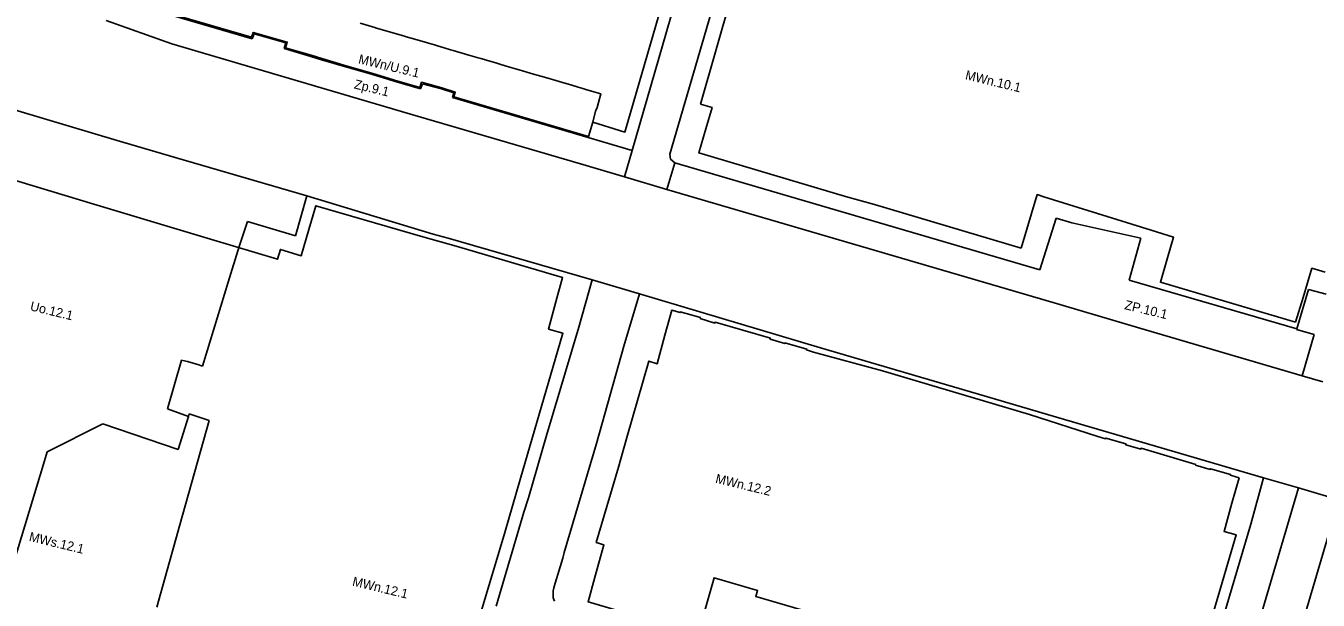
# Model space of a CAD drawing. Extents: x 7429686 to 7432896, y 5547954 to 5550600.
# Drawn here: x 7431434 to 7431990, y 5548459 to 5548706 of the extents above; entities that cross this region are included whole.
import ezdxf

# ---------------------------------------------------------------- set-up
doc = ezdxf.new("R2010")
doc.units = 0
for name, color, linetype in [('linie rozgraniczające', 7, 'Continuous'), ('obowiązująca linia zabudowy', 7, 'Continuous'), ('oznaczenia przeznaczeń', 7, 'Continuous')]:
    doc.layers.add(name, color=color, linetype=linetype)

msp = doc.modelspace()

# ---------------------------------------------------------------- linework, layer by layer
at = {"layer": 'linie rozgraniczające'}
for p, q in [((7431577.76, 5548707.2), (7431584.04, 5548705.36)), ((7431584.04, 5548705.36), (7431584.23, 5548705.3)), ((7431584.23, 5548705.3), (7431590.71, 5548703.4)), ((7431590.71, 5548703.4), (7431594.39, 5548702.33)), ((7431594.39, 5548702.33), (7431597.18, 5548701.51)), ((7431597.18, 5548701.51), (7431597.49, 5548701.42)), ((7431597.49, 5548701.42), (7431600.27, 5548700.6)), ((7431600.27, 5548700.6), (7431603.65, 5548699.61)), ((7431603.65, 5548699.61), (7431604.22, 5548699.45)), ((7431604.22, 5548699.45), (7431606.71, 5548698.72)), ((7431606.71, 5548698.72), (7431610.12, 5548697.72)), ((7431610.12, 5548697.72), (7431610.94, 5548697.48)), ((7431610.94, 5548697.48), (7431613.89, 5548696.61)), ((7431613.89, 5548696.61), (7431616.59, 5548695.82)), ((7431616.59, 5548695.82), (7431617.67, 5548695.51)), ((7431617.67, 5548695.51), (7431623.06, 5548693.93)), ((7431623.06, 5548693.93), (7431624.39, 5548693.54)), ((7431624.39, 5548693.54), (7431628.4, 5548692.36)), ((7431628.4, 5548692.36), (7431629.54, 5548692.03)), ((7431631.5, 5548691.45), (7431636.01, 5548690.13)), ((7431636.01, 5548690.13), (7431637.84, 5548689.6)), ((7431637.84, 5548689.6), (7431640.09, 5548688.94)), ((7431640.09, 5548688.94), (7431642.48, 5548688.24)), ((7431642.48, 5548688.24), (7431644.57, 5548687.63)), ((7431644.57, 5548687.63), (7431645.12, 5548687.46)), ((7431645.12, 5548687.46), (7431648.95, 5548686.34)), ((7431648.95, 5548686.34), (7431651.29, 5548685.66)), ((7431658.01, 5548683.69), (7431661.89, 5548682.55)), ((7431661.89, 5548682.55), (7431664.74, 5548681.72)), ((7431664.74, 5548681.72), (7431668.37, 5548680.65)), ((7431668.37, 5548680.65), (7431671.46, 5548679.75)), ((7431671.46, 5548679.75), (7431673.47, 5548679.16)), ((7431673.47, 5548679.16), (7431674.84, 5548678.76)), ((7431681.2, 5548676.79), (7431680.21, 5548673.18)), ((7431681.22, 5548676.89), (7431681.2, 5548676.79)), ((7431675.72, 5548658.05), (7431617.39, 5548675.21)), ((7431678.98, 5548669.34), (7431677.77, 5548664.65)), ((7431679.1, 5548669.64), (7431678.98, 5548669.34)), ((7431677.77, 5548664.65), (7431675.86, 5548658.53)), ((7431675.86, 5548658.53), (7431675.72, 5548658.05)), ((7431675.72, 5548658.05), (7431694.68, 5548652.52))]:
    msp.add_line(p, q, dxfattribs=at)
for points in [[(7431503.63, 5548920.58), (7431505.97, 5548918), (7431509.04, 5548914.81), (7431512.23, 5548911.8), (7431515.52, 5548908.91), (7431518.64, 5548906.47), (7431521.8, 5548904.16), (7431525.48, 5548901.64), (7431528.82, 5548899.44), (7431532.17, 5548897.4), (7431535.64, 5548895.42), (7431539.13, 5548893.58), (7431542.89, 5548892), (7431546.65, 5548890.61), (7431554.28, 5548888.03), (7431569.39, 5548883.24), (7431746.47, 5548831.23), (7431732.49, 5548783.01), (7431694.68, 5548652.52)], [(7431694.68, 5548652.52), (7431732.49, 5548783.01), (7431746.47, 5548831.23)], [(7431710.91, 5548650.94), (7431731.33, 5548720.67)], [(7431531.3, 5548700.57), (7431472.83, 5548717.66)], [(7431496.71, 5548698.43), (7431468.45, 5548708.34)], [(7431675.72, 5548658.05), (7431675.86, 5548658.53), (7431675.86, 5548658.53), (7431677.77, 5548664.65), (7431678.98, 5548669.34), (7431679.1, 5548669.64), (7431679.6, 5548670.96), (7431680.21, 5548673.18), (7431681.2, 5548676.79), (7431681.22, 5548676.89), (7431678.19, 5548677.78), (7431674.84, 5548678.76), (7431673.47, 5548679.16), (7431671.46, 5548679.75), (7431668.37, 5548680.65), (7431664.74, 5548681.72), (7431661.89, 5548682.55), (7431658.01, 5548683.69), (7431655.42, 5548684.45), (7431651.29, 5548685.66), (7431648.95, 5548686.34), (7431645.12, 5548687.46), (7431644.57, 5548687.63), (7431642.48, 5548688.24), (7431640.09, 5548688.94), (7431637.84, 5548689.6), (7431636.01, 5548690.13), (7431631.5, 5548691.45), (7431631.12, 5548691.57), (7431629.54, 5548692.03), (7431628.4, 5548692.36), (7431624.39, 5548693.54), (7431623.06, 5548693.93), (7431617.67, 5548695.51), (7431616.59, 5548695.82), (7431613.89, 5548696.61), (7431610.94, 5548697.48), (7431610.12, 5548697.72), (7431606.71, 5548698.72), (7431604.22, 5548699.45), (7431603.65, 5548699.61), (7431600.27, 5548700.6), (7431597.49, 5548701.42), (7431597.18, 5548701.51), (7431594.39, 5548702.33), (7431590.71, 5548703.4), (7431584.23, 5548705.3), (7431584.04, 5548705.36), (7431577.76, 5548707.2)], [(7431600.36, 5548667.76), (7431496.71, 5548698.43)], [(7431532.03, 5548702.66), (7431531.3, 5548700.57)], [(7431545.69, 5548698.76), (7431532.03, 5548702.66)], [(7431544.95, 5548696.35), (7431545.69, 5548698.76)], [(7431556.43, 5548692.95), (7431544.95, 5548696.35)], [(7431561.06, 5548691.54), (7431556.43, 5548692.95)], [(7431571.9, 5548688.31), (7431561.06, 5548691.54)], [(7431581.54, 5548685.54), (7431571.9, 5548688.31)], [(7431629.54, 5548692.03), (7431631.12, 5548691.57), (7431631.5, 5548691.45)], [(7431587.72, 5548683.7), (7431581.54, 5548685.54)], [(7431592.37, 5548682.28), (7431587.72, 5548683.7)], [(7431603.71, 5548678.98), (7431592.37, 5548682.28)], [(7431651.29, 5548685.66), (7431655.42, 5548684.45), (7431658.01, 5548683.69)], [(7431604.45, 5548681.2), (7431603.71, 5548678.98)], [(7431612.66, 5548678.95), (7431604.45, 5548681.2)], [(7431617.97, 5548677.21), (7431612.66, 5548678.95)], [(7431617.39, 5548675.21), (7431617.97, 5548677.21)], [(7431674.84, 5548678.76), (7431678.19, 5548677.78), (7431681.22, 5548676.89)], [(7431420.72, 5548672.35), (7431473.1, 5548656.83)], [(7431680.21, 5548673.18), (7431679.6, 5548670.96), (7431679.1, 5548669.64)], [(7431672.44, 5548646.7), (7431600.36, 5548667.76)], [(7431473.1, 5548656.83), (7431498.14, 5548649.42)], [(7431694.68, 5548652.52), (7431675.72, 5548658.05)], [(7431498.14, 5548649.42), (7431554.76, 5548632.95)], [(7431691.39, 5548641.16), (7431694.68, 5548652.52)], [(7431711.13, 5548648.69), (7431710.91, 5548650.94)], [(7431713.04, 5548647.14), (7431711.13, 5548648.69)], [(7431691.39, 5548641.16), (7431672.44, 5548646.7)], [(7431709.65, 5548635.7), (7431713.04, 5548647.14)], [(7431870.15, 5548601.12), (7431713.04, 5548647.14)], [(7431709.65, 5548635.7), (7431691.39, 5548641.16)], [(7431549.94, 5548615.77), (7431554.76, 5548632.95)], [(7431554.76, 5548632.95), (7431609.14, 5548616.53)], [(7431876.24, 5548586.9), (7431709.65, 5548635.7)], [(7431525.64, 5548611.13), (7431529.21, 5548621.93)], [(7431529.21, 5548621.93), (7431549.94, 5548615.77)], [(7431877.06, 5548623.35), (7431870.15, 5548601.12)], [(7431883.87, 5548621.35), (7431877.06, 5548623.35)], [(7431913.57, 5548614.73), (7431883.87, 5548621.35)], [(7431609.14, 5548616.53), (7431615.49, 5548614.69)], [(7431520.93, 5548595.86), (7431525.64, 5548611.13)], [(7431615.49, 5548614.69), (7431677.48, 5548596.82)], [(7431908.52, 5548596.75), (7431913.57, 5548614.73)], [(7431509.85, 5548559.63), (7431520.93, 5548595.86)], [(7431671.82, 5548576.51), (7431677.48, 5548596.82)], [(7431677.48, 5548596.82), (7431697.81, 5548590.8)], [(7431980.62, 5548575.7), (7431908.52, 5548596.75)], [(7431980.62, 5548575.7), (7431985.71, 5548592.71)], [(7431985.71, 5548592.71), (7431993.32, 5548590.62)], [(7431691.12, 5548568.26), (7431697.81, 5548590.8)], [(7431697.81, 5548590.8), (7431775.77, 5548567.61)], [(7431915.54, 5548575.38), (7431876.24, 5548586.9)], [(7431657.81, 5548529.79), (7431671.82, 5548576.51)], [(7431982.95, 5548555.5), (7431915.54, 5548575.38)], [(7431980.55, 5548575.45), (7431980.62, 5548575.7)], [(7431988.11, 5548573.3), (7431980.55, 5548575.45)], [(7431982.95, 5548555.5), (7431988.11, 5548573.3)], [(7431679.35, 5548526.44), (7431691.12, 5548568.26)], [(7431775.77, 5548567.61), (7431846.2, 5548546.87)], [(7431494.74, 5548541.27), (7431500.84, 5548562.3)], [(7431500.84, 5548562.3), (7431502.63, 5548561.86)], [(7431502.63, 5548561.86), (7431503.34, 5548561.65)], [(7431503.34, 5548561.65), (7431508.26, 5548560.22)], [(7431508.26, 5548560.22), (7431509, 5548559.99)], [(7431509, 5548559.99), (7431509.85, 5548559.63)], [(7431991.83, 5548552.89), (7431982.95, 5548555.5)], [(7431846.2, 5548546.87), (7431878.25, 5548537.41)], [(7431503.78, 5548538.02), (7431494.74, 5548541.27)], [(7431499.42, 5548523.89), (7431503.78, 5548538.02)], [(7431504.16, 5548539.22), (7431503.78, 5548538.02)], [(7431512.66, 5548536.29), (7431504.16, 5548539.22)], [(7431878.25, 5548537.41), (7431966.32, 5548511.58)], [(7431443.04, 5548522.77), (7431467.02, 5548534.9)], [(7431467.02, 5548534.9), (7431499.42, 5548523.89)], [(7431500.07, 5548491.36), (7431512.66, 5548536.29)], [(7431650.1, 5548503.07), (7431657.81, 5548529.79)], [(7431665.5, 5548479.5), (7431679.35, 5548526.44)], [(7431441.87, 5548518.94), (7431443.04, 5548522.77)], [(7431426.79, 5548469.23), (7431441.87, 5548518.94)], [(7431960.89, 5548491.66), (7431966.32, 5548511.58)], [(7431966.32, 5548511.58), (7431981.35, 5548507.31)], [(7431957.96, 5548428.04), (7431981.35, 5548507.31)], [(7431981.35, 5548507.31), (7432021.76, 5548495.37)], [(7431648.03, 5548496.92), (7431650.1, 5548503.07)], [(7431636.27, 5548456.43), (7431648.03, 5548496.92)], [(7431490.15, 5548455.95), (7431500.07, 5548491.36)], [(7431934.9, 5548404.14), (7431960.89, 5548491.66)], [(7431661.54, 5548466.27), (7431664.9, 5548477.02)], [(7431664.9, 5548477.02), (7431665.5, 5548479.5)], [(7431661.05, 5548464.33), (7431661.54, 5548466.27)], [(7431660.67, 5548461.65), (7431660.76, 5548462.99)], [(7431660.79, 5548460.09), (7431660.67, 5548461.65)], [(7431660.76, 5548462.99), (7431661.05, 5548464.33)], [(7431661.32, 5548458.6), (7431660.79, 5548460.09)]]:
    msp.add_lwpolyline(points, dxfattribs=at)
at = {"layer": 'obowiązująca linia zabudowy'}
for points in [[(7431773.26, 5548819.35), (7431770.21, 5548808.72), (7431766.52, 5548795.89), (7431760.63, 5548797.5), (7431747.1, 5548751.63), (7431737.24, 5548718.65), (7431724.14, 5548672.46)], [(7431677.77, 5548664.65), (7431691.6, 5548660.41), (7431709.71, 5548723.13), (7431696.9, 5548726.97), (7431692.03, 5548728.43), (7431685.12, 5548730.5), (7431691.1, 5548750.31), (7431692.09, 5548753.03), (7431692.74, 5548752.98), (7431696.32, 5548765.42), (7431709.17, 5548761.44), (7431714.67, 5548759.88), (7431714.76, 5548760.15), (7431720.43, 5548758.57), (7431734.2, 5548805.59)], [(7431474.94, 5548724.18), (7431473.1, 5548718.1), (7431530.98, 5548701.18), (7431531.71, 5548703.27), (7431546.32, 5548699.1), (7431545.58, 5548696.69), (7431556.57, 5548693.43), (7431561.2, 5548692.02), (7431572.04, 5548688.79), (7431581.68, 5548686.02), (7431587.86, 5548684.18), (7431592.51, 5548682.76), (7431603.39, 5548679.59), (7431604.13, 5548681.81), (7431612.8, 5548679.43), (7431618.58, 5548677.53), (7431618.01, 5548675.55), (7431675.86, 5548658.53)], [(7431724.14, 5548672.46), (7431729.1, 5548670.95), (7431726.44, 5548661.83), (7431723.41, 5548651.43), (7431786.46, 5548632.71), (7431799.01, 5548629.2), (7431862.03, 5548610.46)], [(7431661.93, 5548587.41), (7431664.76, 5548597.77), (7431619.01, 5548611.26), (7431604.6, 5548615.26), (7431558.56, 5548628.68), (7431555.6, 5548618.44), (7431552.34, 5548607.16), (7431543.4, 5548609.89), (7431542.19, 5548605.72), (7431513.29, 5548614.38), (7431463.15, 5548629.4), (7431424.62, 5548640.94)], [(7431862.03, 5548610.46), (7431868.97, 5548633.48), (7431871.84, 5548632.59), (7431917.93, 5548618.24), (7431927.66, 5548615.15), (7431925.05, 5548606.25), (7431921.97, 5548595.78), (7431980.11, 5548578.65)], [(7431980.11, 5548578.65), (7431983.32, 5548589.28), (7431987.11, 5548601.81), (7431992.83, 5548600.15)], [(7431628.67, 5548435.65), (7431624.22, 5548436.98), (7431626.46, 5548444.68), (7431627.57, 5548448.49), (7431628.08, 5548448.41), (7431639.98, 5548488.13), (7431646.49, 5548510.93), (7431664.93, 5548573.87), (7431658.72, 5548575.66), (7431661.93, 5548587.41)], [(7431955.79, 5548511.65), (7431952.07, 5548512.75), (7431952.04, 5548513.07), (7431943.5, 5548515.55), (7431943.39, 5548515.27), (7431937.08, 5548517.06), (7431937.17, 5548517.44), (7431913.64, 5548524.39), (7431913.49, 5548524.04), (7431907.06, 5548525.87), (7431907.15, 5548526.23), (7431898.5, 5548528.78), (7431898.35, 5548528.49), (7431895.1, 5548529.49), (7431865.63, 5548538.88), (7431802.44, 5548557.68), (7431772.75, 5548565.71), (7431769.65, 5548566.7), (7431769.81, 5548567.05), (7431760.42, 5548569.71), (7431760.32, 5548569.41), (7431754.06, 5548571.32), (7431754.16, 5548571.71), (7431730.39, 5548578.64), (7431730.24, 5548578.21), (7431723.99, 5548580.16), (7431724.1, 5548580.59), (7431715.32, 5548583.05), (7431715.42, 5548582.71), (7431711.77, 5548583.75), (7431708.82, 5548572.96)], [(7431708.82, 5548572.96), (7431705.49, 5548560.74), (7431701.81, 5548561.88), (7431692.4, 5548529.05), (7431688.85, 5548516.28), (7431679.28, 5548483.84), (7431682.53, 5548482.89), (7431678.53, 5548468.36)], [(7431922.73, 5548400.45), (7431925.69, 5548410.79), (7431931.72, 5548408.99), (7431941.15, 5548441.9), (7431944.91, 5548454.38), (7431954.48, 5548487.17), (7431949.36, 5548488.59), (7431952.75, 5548500.73), (7431955.79, 5548511.65)], [(7432094.69, 5548469.76), (7432095.05, 5548471.04), (7432029.16, 5548490.11), (7432010.6, 5548494.29), (7431997.5, 5548498.35), (7431979.97, 5548438.57)], [(7431678.53, 5548468.36), (7431675.77, 5548458.31), (7431723.14, 5548444.37), (7431726, 5548454.54), (7431729.97, 5548468.66), (7431736.92, 5548466.6), (7431748.64, 5548463.12), (7431747.84, 5548460.58), (7431790.6, 5548448.11), (7431785.1, 5548428.88), (7431794.62, 5548426.27), (7431812.24, 5548421.42), (7431820.72, 5548419.83), (7431832.43, 5548416.4), (7431872.32, 5548404.71), (7431919.77, 5548390.09), (7431922.73, 5548400.45)]]:
    msp.add_lwpolyline(points, dxfattribs=at)

# ---------------------------------------------------------------- texts
at = {"layer": 'oznaczenia przeznaczeń'}
for s, rotation, p in [('MWn/U.9.1', 346.4891, (7431576.65, 5548690.03)), ('Zp.9.1', 346.4891, (7431574.84, 5548679.21)), ('MWn.10.1', 346.4891, (7431837.74, 5548683.16)), ('Uo.12.1', 346.4891, (7431435.45, 5548583.75)), ('ZP.10.1', 346.4891, (7431906.26, 5548584.27)), ('MWn.12.2', 346.4891, (7431730.25, 5548509.56)), ('MWs.12.1', 346.4891, (7431434.97, 5548484.56)), ('MWn.12.1', 346.5122, (7431574.06, 5548465.33))]:
    msp.add_text(s, height=4, rotation=rotation, dxfattribs=at).set_placement(p)

doc.saveas('drawing.dxf')
